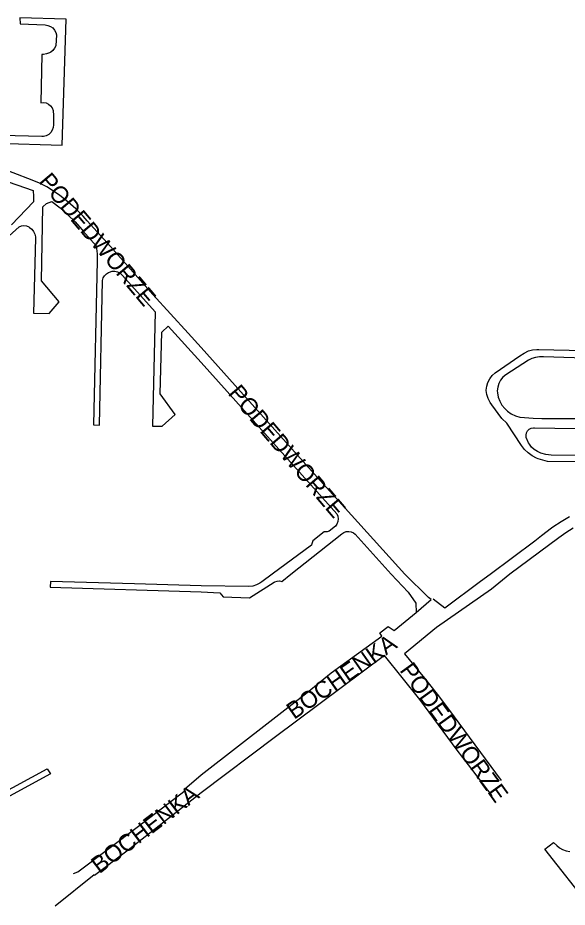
# Model space of a CAD drawing. Extents: x -304109 to -273954, y 21500 to 39796.
# Drawn here: x -291308 to -290984, y 26053 to 26578 of the extents above; entities that cross this region are included whole.
import ezdxf

# ---------------------------------------------------------------- set-up
doc = ezdxf.new("R2010")
doc.units = 0
doc.layers.add('krawedzie_ulic', color=7, linetype='Continuous')
doc.layers.add('nazwy_ulic', color=7, linetype='Continuous')

msp = doc.modelspace()

# ---------------------------------------------------------------- linework, layer by layer
at = {"layer": 'krawedzie_ulic'}
for points in [[(-291320.869, 26504.533), (-291281.964, 26503.265), (-291279.622, 26577.55), (-291306.874, 26578.448), (-291306.701, 26574.786), (-291292.019, 26574.208), (-291290.385, 26573.99), (-291288.852, 26573.386), (-291287.508, 26572.432), (-291286.432, 26571.183), (-291285.688, 26569.713), (-291285.36, 26568.427), (-291285.726, 26561.891), (-291286.383, 26560.438), (-291287.379, 26559.194), (-291288.653, 26558.236), (-291289.446, 26557.852), (-291291.125, 26557.128), (-291292.921, 26556.785), (-291293.875, 26556.764), (-291294.551, 26528.306), (-291292.995, 26528.432), (-291291.458, 26528.16), (-291290.039, 26527.507), (-291288.832, 26526.517), (-291287.915, 26525.254), (-291287.347, 26523.8), (-291287.204, 26523.007), (-291287.053, 26521.506), (-291287.011, 26515.25), (-291287.188, 26513.608), (-291287.753, 26512.057), (-291288.674, 26510.686), (-291289.896, 26509.575), (-291291.348, 26508.79), (-291292.947, 26508.375), (-291293.866, 26508.315), (-291333.28, 26509.304)], [(-291361.443, 26498.074), (-291298.95, 26476.513), (-291298.789, 26472.922), (-291298.893, 26469.898), (-291311.857, 26456.268)], [(-291129.834, 26305.388), (-291200, 26383.828), (-291207.651, 26392.241), (-291228.487, 26415.216), (-291253.536, 26443.414), (-291267.124, 26458.672), (-291269.626, 26461.446), (-291273.956, 26465.767), (-291278.56, 26469.796), (-291283.417, 26473.516), (-291287.049, 26476.198), (-291291.058, 26478.672), (-291295.263, 26480.798), (-291299.632, 26482.559), (-291322.214, 26491.182)], [(-291331.102, 26433.771), (-291307.361, 26455.134), (-291305.96, 26455.678), (-291304.466, 26455.835), (-291302.982, 26455.594), (-291301.615, 26454.972), (-291301.144, 26454.643), (-291299.811, 26453.629), (-291298.754, 26452.328), (-291298.035, 26450.815), (-291297.694, 26449.175), (-291297.669, 26448.473), (-291298.921, 26404.092), (-291289.644, 26403.979), (-291283.647, 26410.743), (-291294.207, 26423.15), (-291293.304, 26466.802), (-291291.191, 26468.834), (-291288.112, 26469.924), (-291283.221, 26466.23), (-291278.582, 26462.225), (-291274.214, 26457.926), (-291270.135, 26453.351), (-291269.667, 26452.785), (-291261.913, 26443.91), (-291261.324, 26439.189), (-291261.38, 26435.07), (-291263.561, 26338.209), (-291260.005, 26338.092), (-291258.2, 26423.362), (-291257.78, 26424.868), (-291256.993, 26426.22), (-291255.89, 26427.328), (-291254.543, 26428.122), (-291253.953, 26428.34), (-291252.458, 26428.8), (-291250.895, 26428.868), (-291249.365, 26428.539), (-291247.968, 26427.834), (-291246.795, 26426.8), (-291246.428, 26426.339), (-291227.129, 26404.854), (-291228.749, 26337.486), (-291223.032, 26337.338), (-291215.252, 26344.234), (-291224.138, 26356.47), (-291223.192, 26392.923), (-291219.49, 26396.49), (-291200, 26374.95), (-291120.069, 26285.722), (-291119.456, 26284.254), (-291119.226, 26282.679), (-291119.395, 26281.097), (-291119.952, 26279.606), (-291120.796, 26278.374), (-291124.547, 26275.494), (-291125.791, 26275.051), (-291127.11, 26274.999), (-291127.439, 26275.049), (-291134.183, 26269.82), (-291134.708, 26267.882), (-291135.029, 26267.131), (-291158.099, 26250), (-291164.185, 26245.581), (-291165.348, 26244.749)], [(-290938.842, 26316.007), (-290995.881, 26316.624), (-291001.235, 26318.158), (-291002.284, 26318.595), (-291004.847, 26319.966), (-291007.199, 26321.674), (-291009.295, 26323.69), (-291011.094, 26325.973), (-291019.821, 26339.163), (-291022.684, 26341.972), (-291028.595, 26349.938), (-291029.686, 26351.469), (-291030.829, 26353.676), (-291031.604, 26356.036), (-291031.99, 26358.491), (-291031.982, 26358.645), (-291031.651, 26360.986), (-291030.931, 26363.238), (-291029.843, 26365.336), (-291028.416, 26367.221), (-291026.693, 26368.839), (-291012.202, 26378.902), (-291009.592, 26380.576), (-291006.974, 26381.825), (-291004.591, 26382.472), (-291002.135, 26382.725), (-291001.013, 26382.709), (-290929.626, 26380.993)], [(-290950.063, 26376.761), (-290998.141, 26378.246), (-291000.501, 26378.339), (-291002.844, 26378.034), (-291005.101, 26377.338), (-291007.066, 26376.359), (-291020.408, 26367.676), (-291022.062, 26366.24), (-291023.429, 26364.527), (-291024.462, 26362.595), (-291025.127, 26360.508), (-291025.403, 26358.334), (-291025.383, 26357.112), (-291024.854, 26354.567), (-291023.942, 26352.133), (-291022.667, 26349.868), (-291021.06, 26347.825), (-291019.459, 26346.297), (-291017.179, 26344.767), (-291014.701, 26343.585), (-291012.078, 26342.775), (-291011.947, 26342.745), (-291004.285, 26342.172), (-290999.135, 26342.012)], [(-290999.135, 26342.012), (-290939.583, 26341.931)], [(-290939.98, 26319.969), (-290993.725, 26320.279), (-290996.751, 26320.705), (-290999.695, 26321.523), (-291001.804, 26322.377), (-291003.629, 26323.544), (-291005.208, 26325.027), (-291006.488, 26326.774), (-291006.935, 26327.59), (-291008.335, 26330.723), (-291008.481, 26332.067), (-291008.23, 26333.395), (-291007.602, 26334.592), (-291006.654, 26335.555), (-291005.466, 26336.2), (-291004.142, 26336.471), (-291003.477, 26336.459)], [(-291003.477, 26336.459), (-290943.122, 26335.482)], [(-291073.314, 26227.404), (-291064.334, 26235.066), (-291066.042, 26236.29), (-291079.957, 26250), (-291129.782, 26305.412)], [(-291063.234, 26235.48), (-291056.435, 26230.1), (-291035.238, 26245.853), (-291029.705, 26250), (-291003.302, 26269.755), (-290999.422, 26272.913), (-290993.437, 26277.354), (-290992.631, 26277.947), (-290987.824, 26281.19), (-290982.804, 26284.094)], [(-291288.761, 26245.72), (-291289.063, 26242.414), (-291200, 26239.676), (-291189.013, 26239.048), (-291187.069, 26236.751), (-291171.543, 26236.162), (-291156.867, 26245.307), (-291156.576, 26245.472), (-291155.231, 26245.954), (-291153.805, 26246.047), (-291152.409, 26245.742), (-291147.16, 26250), (-291117.013, 26273.773), (-291115.82, 26274.652), (-291114.435, 26275.181), (-291112.96, 26275.323), (-291111.5, 26275.067), (-291110.161, 26274.431), (-291109.26, 26273.697), (-291087.915, 26250), (-291078.017, 26239.339), (-291073.5, 26232.877), (-291073.314, 26227.404)], [(-290980.761, 26277.201), (-290985.014, 26274.545), (-290989.041, 26271.559), (-291018.113, 26250), (-291028.909, 26241.27), (-291061.287, 26218.527), (-291080.167, 26202.99), (-291068.361, 26188.647), (-291060.849, 26179.185), (-291054.259, 26170.321), (-291023.173, 26128.178)], [(-291165.348, 26244.749), (-291167.381, 26243.692), (-291169.566, 26243.004), (-291171.837, 26242.706), (-291200, 26243.236), (-291239.286, 26244.292), (-291288.761, 26245.72)], [(-291275.356, 26073.464), (-291272.689, 26074.28), (-291236.886, 26101.419), (-291209.488, 26122.347), (-291209.896, 26123.084), (-291199.988, 26131.603), (-291137.569, 26180.129), (-291123.331, 26191.876), (-291093.413, 26213.439), (-291094.752, 26215.42), (-291089.729, 26219.204), (-291086.236, 26216.78), (-291073.314, 26227.404)], [(-291028.414, 26119.131), (-291042.364, 26137.453), (-291048.979, 26146.138), (-291071.119, 26176.149), (-291091.829, 26202.09), (-291156.248, 26154.105), (-291200, 26120.957), (-291230.351, 26097.154), (-291243.834, 26086.665), (-291262.929, 26072.255), (-291263.031, 26072.585), (-291286.035, 26054.129)], [(-291378.917, 26087.35), (-291290.713, 26135.11), (-291288.728, 26132.264), (-291365.91, 26090.261)], [(-290970.424, 26053.488), (-290997.348, 26087.725), (-290992.372, 26091.688), (-290990.268, 26089.821), (-290988.778, 26088.58), (-290986.878, 26087.487), (-290984.812, 26086.756), (-290982.648, 26086.412)]]:
    msp.add_lwpolyline(points, dxfattribs=at)

# ---------------------------------------------------------------- texts
at = {"layer": 'nazwy_ulic'}
for s, rotation, p in [('PODEDWORZE', 310.17159, (-291296.262, 26481.634)), ('PODEDWORZE', 310.29188, (-291184.595, 26356.558)), ('BOCHENKA', 35.00062, (-291145.184, 26163.998)), ('PODEDWORZE', 305.82281, (-291083.346, 26193.293)), ('BOCHENKA', 37.37088, (-291259.999, 26072.913))]:
    msp.add_text(s, height=10, rotation=rotation, dxfattribs=at).set_placement(p)

doc.saveas('drawing.dxf')
